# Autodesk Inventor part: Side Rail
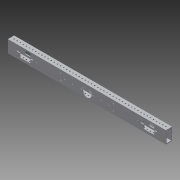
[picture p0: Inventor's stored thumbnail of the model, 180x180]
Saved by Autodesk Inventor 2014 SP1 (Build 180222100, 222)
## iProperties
Created: 2014-06
Part Number: Side Rail
Material: Aluminum 6061
Document SubType Name: Modeling
Designer: Michael
Density: 2.71 g/cm^3
Appearance: Aluminum - Flat
Mass: 694.789 g
Surface Area: 1710.8 cm^2
Volume: 256.38 cm^3
Author: Michael
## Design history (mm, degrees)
sketch "Sketch1"
  geometry: L1 (-323.85, -25.4)-(323.85, -25.4); L2 (323.85, -25.4)-(323.85, 25.4); L3 (323.85, 25.4)-(-323.85, 25.4); L4 (-323.85, 25.4)-(-323.85, -25.4); L5 (-323.85, -25.4)-(323.85, 25.4); L6 (323.85, -25.4)-(-323.85, 25.4); 1 further point
  constraints: 12 end point, 2 midpoint, 2 parallel, 1 horizontal, 1 perpendicular
  dimensions: "d2" = 323.85 distance from line of point (0, 0) L4; "d3" = 50.8 distance between parallel lines of L1 L3
extrude "Extrusion1" new body sketch "Sketch1" stored distance "d4" = 25.4; taper "d5" = 0 deg
sketch "Sketch2"
  geometry: L1 (25.4, 50.8)-(0, 50.8) reference; L2 (0, 0)-(0, 50.8) reference; L3 (25.4, 0)-(0, 0) reference; L4 (25.4, 50.8)-(25.4, 0) reference; L5 (22.225, 3.175)-(3.175, 3.175); L6 (3.175, 3.175)-(3.175, 47.625); L7 (3.175, 47.625)-(22.225, 47.625); L8 (22.225, 47.625)-(22.225, 3.175); 1 further point
  constraints: 8 end point, 3 other
  dimensions: "d6" = 3.175 distance between parallel lines of L1 L7
extrude "Extrusion2" cut sketch "Sketch2" stored distance "d7" = 25.4; taper "d8" = 0 deg
sketch "Sketch3"
  geometry: L1 (-323.85, 25.4)-(-323.85, -25.4) reference; L2 (-19.113, -20.637)-(19.114, -20.637); L3 (19.114, -20.637)-(19.114, 17.59); L4 (19.114, 17.59)-(-19.113, 17.59); L5 (-19.113, 17.59)-(-19.113, -20.637); L6 (-19.113, -20.637)-(19.114, 17.59); L7 (19.114, -20.637)-(-19.113, 17.59); L8 (-276.225, -15.081)-(-231.775, -15.081); L9 (-231.775, 19.971)-(-276.225, 19.971); L10 (-285.75, 4.934)-(-276.225, 4.934); L11 (-285.75, -0.044)-(-276.225, -0.044); L12 (-254, 19.971)-(-254, -15.081); L13 (-222.25, 4.934)-(-231.775, 4.934); L14 (-222.25, -0.044)-(-231.775, -0.044); L15 (0, 17.59)-(0, -20.637); L16 (-276.225, 19.971)-(-276.225, 4.934); L17 (-276.225, -0.044)-(-276.225, -15.081); L18 (-231.775, -15.081)-(-231.775, -0.044); L19 (-231.775, 4.934)-(-231.775, 19.971); L20 (276.225, 19.971)-(276.225, 4.934); L21 (276.225, -0.044)-(276.225, -15.081); L22 (285.75, 4.934)-(276.225, 4.934); L23 (285.75, -0.044)-(276.225, -0.044); L24 (276.225, -15.081)-(231.775, -15.081); L25 (231.775, -15.081)-(231.775, -0.044); L26 (276.225, -15.081)-(231.775, 19.971); L27 (231.775, 19.971)-(276.225, 19.971); L28 (231.775, 4.934)-(231.775, 19.971); L29 (222.25, 4.934)-(231.775, 4.934); L30 (222.25, -0.044)-(231.775, -0.044); L31 (254, 19.971)-(254, -15.081); L32 (-323.85, -25.4)-(323.85, -25.4) reference; C1 r 2.489 at (-23.812, -1.524); C2 r 2.489 at (23.812, -1.524); C3 r 19.114 at (0, -1.524); A1 r 2.489 centre (-285.75, 2.445) between (-285.75, 4.934) and (-285.75, -0.044); A2 r 2.489 centre (-222.25, 2.445) between (-222.25, -0.044) and (-222.25, 4.934); A3 r 2.489 centre (285.75, 2.445) between (285.75, -0.044) and (285.75, 4.934); A4 r 2.489 centre (222.25, 2.445) between (222.25, 4.934) and (222.25, -0.044); 7 further points; 1 other entity
  constraints: 60 end point, 22 symmetric about line, 9 midpoint, 8 point on circle, 7 centre point, 7 parallel, 7 perpendicular, 3 tangent, 2 horizontal, 2 horizontal alignment, 1 coincident, 1 vertical alignment, 8 other
  dimensions: "d10" = 38.227 distance between parallel lines of L3 L5; "d11" = 38.227 distance between parallel lines of L2 L4 (= d10); "d12" = 35.052 distance between parallel lines of L8 L9; "d17" = 4.9784 diameter of A1; "d19" = 44.45 distance between parallel lines of L19 L16; "d20" = 44.45 distance between parallel lines of L18 L17; "d25" = 4.9784 diameter of C1; "d26" = 23.8125 distance of point (0, -1.524) C1.centre; "d48" = 23.876 distance from line of L32 point (0, -1.524) (derived); "d49" = 23.876 distance from line of L32 C2.centre (= d48); "d50" = 31.75 distance of A1.centre point (-254, 2.445); "d51" = 69.85 distance from line of L1 point (-254, 2.445); "d52" = 3.96875 vertical distance of point (0, -1.524) point (-254, 2.445); "d53" = 4.7625 distance between parallel lines of L32 L2
extrude "Extrusion3" cut sketch "Sketch3" stored distance "d21" = 25.4; taper "d22" = 0 deg
fillet "Fillet1" dims "d23" = 3.175
sketch "Sketch4"
  geometry: L1 (0, 25.4)-(0, 0) reference; C1 r 2.489 at (12.7, 12.7); 2 further points
  constraints: 1 centre point, 1 horizontal alignment, 1 midpoint
  dimensions: "d28" = 4.9784 diameter of C1; "d29" = 12.7 distance from line of L1 C1.centre
extrude "Extrusion4" cut sketch "Sketch4" stored distance "d30" = 25.4; taper "d31" = 0 deg
mirror "Mirror1"
sketch "Sketch5"
  geometry: 1 further point
hole "Hole1" sketch "Sketch5" at (323.85, 12.7) diameter "d35" = 4.9784; stored, may be unused: countersink angle "d39" = 82 deg, drill point angle "d41" = 118 deg; dims "d36" = 19.05, "d37" = 9.525, "d38" = 6.35, "d40" = 25.4
sketch "Sketch6"
  geometry: C1 r 2.019 at (207.081, 2.445); C2 r 6.325 at (207.081, 2.445); A1 r 2.489 centre (222.25, 2.445) between (222.25, 4.934) and (222.25, -0.044) reference; 1 further point
  constraints: 2 centre point, 1 coincident, 1 horizontal alignment
  dimensions: "d42" = 4.0386 diameter of C1; "d43" = 12.6492 diameter of C2; "d47" = 15.16924 distance of A1.centre C1.centre
extrude "Extrusion5" cut sketch "Sketch6" stored distance "d44" = 3.175; taper "d45" = 0 deg
mirror "Mirror2"
sketch "Sketch8"
  geometry: L1 (-323.85, 25.4)-(-323.85, -25.4) reference; L2 (0, -1.524)-(0, 0); L3 (0, 0)-(0, -2.872); C1 r 19.114 at (0, -1.524) reference; C2 r 2.489 at (-58.674, -1.524); C3 r 2.489 at (91.237, -1.524); C4 r 2.489 at (58.674, -1.524); C5 r 2.489 at (-91.237, -1.524)
  constraints: 4 centre point, 4 end point, 2 horizontal alignment, 2 symmetric about line, 1 collinear, 1 parallel, 2 other
  dimensions: "d56" = 4.9784 diameter of C2 (derived); "d57" = 58.674 horizontal distance of L2.end C2.centre; "d58" = 4.9784 diameter of C3; "d59" = 91.23719 distance of C3.centre L2.start
extrude "Extrusion6" cut sketch "Sketch8" stored distance "d60" = 25.4; taper "d61" = 0 deg
sketch "Sketch9"
  geometry: L1 (-323.85, -25.4)-(323.85, -25.4) reference; L2 (323.85, 25.4)-(-323.85, 25.4) reference; L3 (-323.85, 25.4)-(-323.85, -25.4) reference; C1 r 2.489 at (-107.95, -12.7); C2 r 2.489 at (-107.95, 12.7); 1 further point
  constraints: 2 centre point, 1 vertical alignment
  dimensions: "d62" = 4.9784 diameter of C1; "d63" = 215.9 distance from line of L3 C1.centre; "d64" = 12.7 distance from line of L1 C1.centre; "d65" = 4.9784 diameter of C2 (derived); "d66" = 12.7 distance from line of L2 C2.centre (derived)
extrude "Extrusion7" cut sketch "Sketch9" stored distance "d67" = 25.4; taper "d68" = 0 deg
mirror "Mirror3"
sketch "Sketch10" dims "d77" = 2.38125
  geometry: L1 (-323.85, 25.4)-(-323.85, -25.4) reference; L2 (-39.37, 22.603)-(-34.755, 22.603); C1 r 2.489 at (-39.37, 21.412) reference; C2 r 2.489 at (39.37, 21.412) reference; 2 further points
  constraints: 2 end point, 1 coincident, 1 horizontal, 1 perpendicular, 1 vertical alignment, 2 other
hole "Hole2" sketch "Sketch10" at (-39.37, 21.412), (39.37, 21.412) diameter "d69" = 1.524; stored, may be unused: countersink angle "d73" = 82 deg, drill point angle "d75" = 118 deg; dims "d70" = 19.05, "d71" = 9.525, "d72" = 6.35, "d74" = 25.4
sketch "Sketch11" dims "d48" = 23.876 (derived), "d49" = 23.876 (= d48)
  geometry: L1 (276.225, 16.796)-(276.225, 4.934) reference; L2 (276.225, 4.934)-(285.75, 4.934) reference; L3 (285.75, -0.044)-(276.225, -0.044) reference; L4 (276.225, -0.044)-(276.225, -11.906) reference; L5 (273.05, -15.081)-(234.95, -15.081) reference; L6 (231.775, -11.906)-(231.775, -0.044) reference; L7 (231.775, -0.044)-(222.25, -0.044) reference; L8 (222.25, 4.934)-(231.775, 4.934) reference; L9 (231.775, 4.934)-(231.775, 16.796) reference; L10 (234.95, 19.971)-(273.05, 19.971) reference; L11 (-231.775, -0.044)-(-231.775, -11.906) reference; L12 (-234.95, -15.081)-(-273.05, -15.081) reference; L13 (-276.225, -11.906)-(-276.225, -0.044) reference; L14 (-276.225, -0.044)-(-285.75, -0.044) reference; L15 (-285.75, 4.934)-(-276.225, 4.934) reference; L16 (-276.225, 4.934)-(-276.225, 16.796) reference; L17 (-273.05, 19.971)-(-234.95, 19.971) reference; L18 (-231.775, 16.796)-(-231.775, 4.934) reference; L19 (-231.775, 4.934)-(-222.25, 4.934) reference; L20 (-222.25, -0.044)-(-231.775, -0.044) reference; L21 (-323.85, -25.4)-(323.85, -25.4) reference; L22 (323.85, -25.4)-(323.85, 25.4) reference; L23 (323.85, 25.4)-(-323.85, 25.4) reference; L24 (-323.85, 25.4)-(-323.85, -25.4) reference; L25 (-120.65, -25.4)-(-95.25, -25.4); L26 (-95.25, -25.4)-(-95.25, 25.4); L27 (-95.25, 25.4)-(-120.65, 25.4); L28 (-120.65, 25.4)-(-120.65, -25.4); L29 (-120.65, -25.4)-(-95.25, 25.4); L30 (-95.25, -25.4)-(-120.65, 25.4); L31 (323.85, 22.225)-(-323.85, 22.225) reference; L32 (323.85, -22.225)-(-323.85, -22.225) reference; L33 (-248.446, 27.23)-(-138.26, 2.542); L34 (-157.26, -2.53)-(-248.607, -22.376); L35 (-154.316, -2.45)-(-4.03, -26.602); L36 (-135.265, 2.45)-(-4.033, 23.554); L37 (-4.033, 23.554)-(0, -1.524); L38 (0, -1.524)-(-4.03, -26.602); L39 (0, -1.524)-(0, -19.761); L40 (0, -19.761)-(0, 16.362); C1 r 0.762 at (39.37, 21.412) reference; C2 r 0.762 at (-39.37, 21.412) reference; C3 r 2.489 at (107.95, 12.7) reference; C4 r 2.489 at (107.95, -12.7) reference; C5 r 2.489 at (-107.95, -12.7) reference; C6 r 2.489 at (-107.95, 12.7) reference; C7 r 2.489 at (58.674, -1.524) reference; C8 r 2.489 at (-58.674, -1.524) reference; C9 r 2.489 at (91.237, -1.524) reference; C10 r 2.489 at (-91.237, -1.524) reference; C11 r 2.019 at (207.081, 2.445) reference; C12 r 2.019 at (-207.081, 2.445) reference; C13 r 2.489 at (23.812, -1.524) reference; C14 r 2.489 at (-23.812, -1.524) reference; C15 r 19.114 at (0, -1.524) reference; C16 r 11.112 at (-136.525, 10.287); C17 r 11.113 at (-155.575, -10.287); C18 r 9.525 at (-91.237, -1.524); A1 r 2.489 centre (285.75, 2.445) between (285.75, -0.044) and (285.75, 4.934) reference; A2 r 3.175 centre (273.05, -11.906) between (273.05, -15.081) and (276.225, -11.906) reference; A3 r 3.175 centre (234.95, -11.906) between (231.775, -11.906) and (234.95, -15.081) reference; A4 r 2.489 centre (222.25, 2.445) between (222.25, 4.934) and (222.25, -0.044) reference; A5 r 3.175 centre (234.95, 16.796) between (234.95, 19.971) and (231.775, 16.796) reference; A6 r 3.175 centre (273.05, 16.796) between (276.225, 16.796) and (273.05, 19.971) reference; A7 r 3.175 centre (-234.95, -11.906) between (-234.95, -15.081) and (-231.775, -11.906) reference; A8 r 3.175 centre (-273.05, -11.906) between (-276.225, -11.906) and (-273.05, -15.081) reference; A9 r 2.489 centre (-285.75, 2.445) between (-285.75, 4.934) and (-285.75, -0.044) reference; A10 r 3.175 centre (-273.05, 16.796) between (-273.05, 19.971) and (-276.225, 16.796) reference; A11 r 3.175 centre (-234.95, 16.796) between (-231.775, 16.796) and (-234.95, 19.971) reference; A12 r 2.489 centre (-222.25, 2.445) between (-222.25, -0.044) and (-222.25, 4.934) reference; A13 r 25.4 centre (-254, 2.445) between (-248.446, 27.23) and (-248.607, -22.376); A14 r 25.4 centre (0, -1.524) between (-4.03, -26.602) and (-4.033, 23.554); A15 r 7.938 centre (-155.575, -10.287) between (-157.26, -2.53) and (-154.316, -2.45); A16 r 7.938 centre (-136.525, 10.287) between (-138.26, 2.542) and (-135.265, 2.45); 4 further points
  constraints: 28 end point, 8 point on circle, 8 tangent, 7 centre point, 4 coincident, 4 midpoint, 4 perpendicular, 2 parallel, 2 point on line, 2 vertical alignment, 1 collinear, 1 horizontal, 1 horizontal alignment
  dimensions: "d78" = 50.8 diameter of A13 (derived); "d79" = 25.4 distance of L27.end L26.end; "d80" = 50.8 diameter of A14; "d81" = 22.225 diameter of C16 (derived); "d82" = 22.225 diameter of C17; "d83" = 19.05 horizontal distance of C17.centre C16.centre; "d85" = 11.938 distance from line of L31 C16.centre; "d86" = 11.938 distance from line of L32 C17.centre (derived); "d87" = 15.875 diameter of A15; "d88" = 15.875 diameter of A16 (derived); "d90" = 19.05 diameter of C18; "d91" = 15.875 distance from line of L28 C16.centre
body "Solid1"
pattern_linear "Rectangular Pattern1" dims "d34" = 12.7
node "Reference2"
node "Reference3"
other parameters: "d14" = 44.45
